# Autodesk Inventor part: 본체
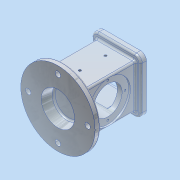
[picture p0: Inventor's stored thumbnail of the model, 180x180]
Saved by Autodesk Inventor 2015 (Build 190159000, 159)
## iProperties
Created: 2018-10
Part Number: 본체
Material: 알루미늄 6061
Document SubType Name: Modeling
Designer: user
Mass: 984.575 g
Surface Area: 743.905 cm^2
Volume: 364.657 cm^3
Density: 2.7 g/cm^3
Appearance: 알루미늄 - 평지
Author: user
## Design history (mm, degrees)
sketch "스케치1"
  geometry: L1 (33, 37)-(-33, 37); L2 (-33, 37)-(-33, -37); L3 (-33, -37)-(33, -37); L4 (33, -37)-(33, 37); L5 (33, 37)-(-33, -37); L6 (-33, 37)-(33, -37); 1 further point
  constraints: 12 end point, 2 midpoint, 2 parallel, 1 horizontal, 1 perpendicular
  dimensions: "d0" = 66 distance of L3.end L2.end; "d1" = 74 distance of L2.end L1.end
extrude "돌출1" new body sketch "스케치1" distance "d2" = 108; taper "d3" = 0 deg
sketch "스케치2"
  geometry: L1 (-33, 37)-(33, 37) reference; L2 (-33, -37)-(-33, 37) reference; L3 (33, -37)-(-33, -37) reference; L4 (33, 37)-(33, -37) reference; C1 r 62.5 at (0, 0); 1 further point
  constraints: 1 centre point, 1 coincident
  dimensions: "d4" = 125 diameter of C1
extrude "돌출2" join sketch "스케치2" distance "d5" = 10; taper "d6" = 0 deg
sketch "스케치3"
  geometry: L1 (-33, -37)-(33, -37) reference; L2 (33, -37)-(33, 37) reference; L3 (33, 37)-(-33, 37) reference; L4 (-33, 37)-(-33, -37) reference; L5 (-41, -46)-(41, -46); L6 (41, -46)-(41, 46); L7 (41, 46)-(-41, 46); L8 (-41, 46)-(-41, -46); L9 (-41, -46)-(41, 46); L10 (41, -46)-(-41, 46); 1 further point
  constraints: 12 end point, 2 midpoint, 2 parallel, 1 horizontal, 1 perpendicular
  dimensions: "d7" = 82 distance of L7.end L6.end; "d8" = 92 distance of L6.end L5.end
extrude "돌출3" join sketch "스케치3" distance "d9" = 10; taper "d10" = 0 deg
sketch "스케치4"
  geometry: C1 r 62.5 at (0, 0) reference; C2 r 28 at (0, 0)
  constraints: 1 centre point, 1 coincident
  dimensions: "d11" = 56 diameter of C2
extrude "돌출4" cut sketch "스케치4" distance "d12" = 18; taper "d13" = -10 deg
sketch "스케치5"
  geometry: L1 (-22, -22)-(22, -22); L2 (22, -22)-(22, 22); L3 (22, 22)-(-22, 22); L4 (-22, 22)-(-22, -22); L5 (-22, -22)-(22, 22); L6 (22, -22)-(-22, 22); 1 further point
  constraints: 12 end point, 2 midpoint, 2 parallel, 1 horizontal, 1 perpendicular
  dimensions: "d14" = 44 distance of L3.end L2.end; "d15" = 44 distance of L2.end L1.end
extrude "돌출5" cut sketch "스케치5" distance "d16" = 82; taper "d17" = 0 deg
sketch "스케치6"
  geometry: L1 (22, 22)-(22, -22) reference; L2 (22, -22)-(-22, -22) reference; L3 (-22, -22)-(-22, 22) reference; L4 (-22, 22)-(22, 22) reference; L5 (-26, -26)-(26, -26); L6 (26, -26)-(26, 26); L7 (26, 26)-(-26, 26); L8 (-26, 26)-(-26, -26); L9 (-26, -26)-(26, 26); L10 (26, -26)-(-26, 26); 1 further point
  constraints: 12 end point, 2 midpoint, 2 parallel, 1 horizontal, 1 perpendicular
  dimensions: "d18" = 52 distance of L7.end L6.end; "d19" = 52 distance of L6.end L5.end
extrude "돌출6" cut sketch "스케치6" distance "d20" = 8; taper "d21" = 0 deg
sketch "스케치7"
  geometry: L1 (99.5, -10)-(-25.5, -10) reference; C1 r 24 at (37, 44); 1 further point
  constraints: 1 centre point, 1 vertical alignment
  dimensions: "d22" = 48 diameter of C1; "d23" = 54 distance from line of L1 C1.centre
fillet "모깎기1" dims "d24" = 3
fillet "모깎기2" dims "d25" = 3
fillet "모깎기3" dims "d26" = 3
extrude "돌출7" cut sketch "스케치7" stored distance "d27" = 8; taper "d28" = 0 deg
sketch "스케치8"
  geometry: C1 r 24 at (37, 44) reference; C2 r 35 at (37, 44); 1 further point
  constraints: 1 centre point, 1 coincident
  dimensions: "d29" = 70 diameter of C2
extrude "돌출8" cut sketch "스케치8" distance "d30" = 3; taper "d31" = 0 deg
sketch "스케치9"
  geometry: C1 r 24 at (0, 0) reference; 2 further points
  constraints: 1 vertical alignment
  dimensions: "d32" = 29 distance of C1.centre point (0, 29)
hole "구멍1" sketch "스케치9" at (0, 29) diameter "d33" = 3.242; stored, may be unused: countersink angle "d37" = 90 deg, drill point angle "d39" = 118 deg; dims "d34" = 4, "d35" = 4, "d36" = 2, "d38" = 6
sketch "스케치10"
  geometry: L1 (95.5, -10)-(-29.5, -10) reference; 3 further points
  constraints: 2 vertical alignment
  dimensions: "d43" = 37 distance from line of L1 point (33, 27); "d44" = 43 distance of point (33, 70) point (33, 27)
hole "구멍2" sketch "스케치10" at (33, 27), (33, 70) diameter "d45" = 4.134; stored, may be unused: countersink angle "d49" = 90 deg, drill point angle "d51" = 118 deg; dims "d46" = 10, "d47" = 4, "d48" = 2, "d50" = 30
sketch "스케치11"
  geometry: C1 r 62.5 at (0, 0) reference; C2 r 4.5 at (0, 50)
  constraints: 1 centre point, 1 vertical alignment
  dimensions: "d52" = 9 diameter of C2; "d53" = 50 distance of C1.centre C2.centre
extrude "돌출9" cut sketch "스케치11" stored distance "d54" = 3; taper "d55" = 0 deg
sketch "스케치12"
  geometry: L1 (-31, 36)-(31, 36); L2 (31, 36)-(31, -36); L3 (31, -36)-(-31, -36); L4 (-31, -36)-(-31, 36); L5 (-31, 36)-(31, -36); L6 (31, 36)-(-31, -36); 5 further points
  constraints: 12 end point, 4 coincident, 2 midpoint, 2 parallel, 1 horizontal, 1 perpendicular
  dimensions: "d59" = 62 distance of L2.end L3.end; "d60" = 72 distance of L1.end L2.end
hole "구멍3" sketch "스케치12" at (31, 36), (31, -36), (-31, -36), (-31, 36) diameter "d61" = 3.242; stored, may be unused: countersink angle "d65" = 90 deg, drill point angle "d67" = 118 deg; dims "d62" = 4, "d63" = 4, "d64" = 2, "d66" = 6
fillet "모깎기4" dims "d68" = 10
chamfer "모따기1" distance "d69" = 1; stored, may be unused: second distance "d70" = 2, angle "d71" = 45 deg
chamfer "모따기2" distance "d72" = 1; stored, may be unused: second distance "d73" = 2, angle "d74" = 45 deg
fillet "모깎기5" dims "d75" = 3
fillet "모깎기6" dims "d76" = 3
fillet "모깎기7" dims "d77" = 3
fillet "모깎기8" dims "d78" = 3
sketch "스케치13"
  geometry: L1 (0, 0)-(72, 0) reference; L2 (-10, 0)-(-10, -10) reference; 2 further points
  constraints: 1 other
  dimensions: "d79" = 46 distance from line of point (36, -4) L2; "d80" = 4 distance from line of L1 point (36, -4)
fillet "모깎기9" dims "d81" = 3
feature "엠보싱1" dims "d82" = 0.5, "d83" = 0
fillet "모깎기10" dims "d84" = 3
node "솔리드1"
pattern_circular "원형 패턴1" dims angle "d41" = 360 deg
mirror "대칭1"
pattern_circular "원형 패턴2" dims angle "d57" = 360 deg
